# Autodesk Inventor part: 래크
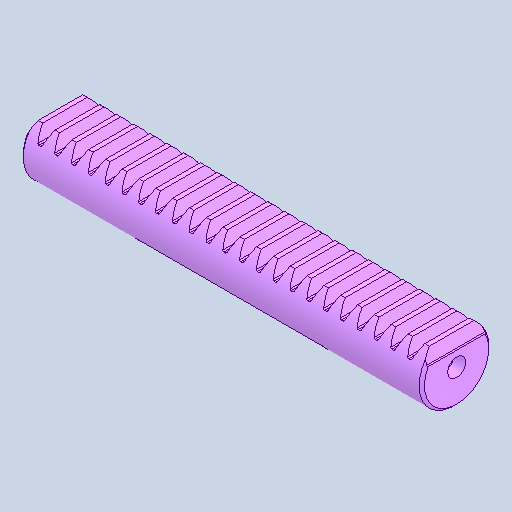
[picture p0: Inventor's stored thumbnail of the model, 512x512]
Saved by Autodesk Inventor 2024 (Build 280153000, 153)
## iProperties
Created: 2024-10
Part Number: 래크
Material: 강철, 탄소
Document SubType Name: Modeling
Designer: user
Density: 7.85 g/cm^3
Appearance: 기본값
Author: jhkim
Sending System: Autodesk Inventor 2025
Preprocessor: ST-DEVELOPER v20
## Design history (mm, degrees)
feature "솔리드1"
node "솔리드2"
